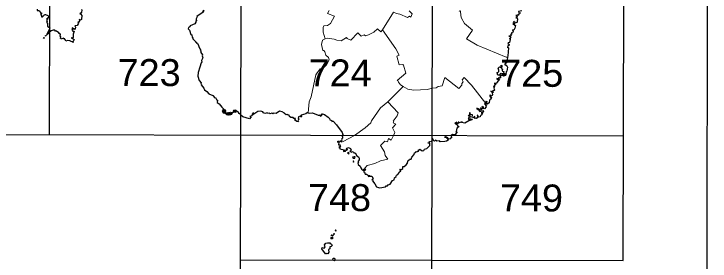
# Model space of a CAD drawing. Extents: x 483855 to 488461, y 4388206 to 4391419.
# Drawn here: x 487957 to 488461, y 4390095 to 4390274 of the extents above; entities that cross this region are included whole.
import ezdxf
from ezdxf.enums import TextEntityAlignment as Align

# ---------------------------------------------------------------- set-up
doc = ezdxf.new("R2010")
doc.units = 0
doc.header["$LTSCALE"] = 4
doc.header["$PDMODE"] = 32
doc.header["$PDSIZE"] = 2
doc.linetypes.add('DOTTED', pattern=[1.5, 0.3, -1.2])
for name, color, linetype, lineweight in [('1', 7, 'Continuous', 13), ('2', 7, 'DOTTED', 13), ('3', 7, 'Continuous', 25)]:
    doc.layers.add(name, color=color, linetype=linetype, lineweight=lineweight)

msp = doc.modelspace()

# ---------------------------------------------------------------- linework, layer by layer
at = {"layer": '1', "lineweight": 25}
for p, q in [((487982.46, 4390186.29), (487983.15, 4390547.6)), ((488120.68, 4390005.39), (488121.71, 4390547.34)), ((488259.24, 4390005.13), (488260.27, 4390547.08)), ((488397.97, 4390095.17), (488398.83, 4390546.81)), ((487843.9, 4390186.56), (488398.14, 4390185.5)), ((488120.85, 4390095.7), (488397.97, 4390095.17))]:
    msp.add_line(p, q, dxfattribs=at)
msp.add_lwpolyline([(483860.86, 4391419.44), (488460.85, 4391410.69), (488454.76, 4388205.69), (483854.77, 4388214.44)], close=True, dxfattribs=at)
at = {"layer": '3', "lineweight": 13}
msp.add_line((488238.58, 4390221.21), (488227.38, 4390210.16), dxfattribs=at)
at = {"layer": '3'}
for points in [[(487973.52, 4390277.25), (487973.36, 4390276.19), (487974.61, 4390276.26), (487975.37, 4390275.8), (487975.64, 4390274.84), (487976.5, 4390274.46), (487976.69, 4390273.83), (487975.88, 4390273.77), (487976.33, 4390273.63), (487976, 4390272.99), (487976.48, 4390272.85), (487976.5, 4390271.77), (487977.2, 4390271.6), (487978.56, 4390272.83)], [(488005.48, 4390277.01), (488005.76, 4390276.78), (488005.64, 4390274.75), (488004.45, 4390273.84), (488005.27, 4390273.88), (488005.24, 4390273.2), (488005.68, 4390272.99), (488005.44, 4390269.65), (488004.93, 4390269.15), (488003.86, 4390269.82), (488004.14, 4390268.43), (488003.66, 4390267.67), (488003.48, 4390267.97), (488002.96, 4390267.83), (488003.07, 4390267.53)], [(488093.48, 4390276.48), (488094.07, 4390276.17), (488093.76, 4390275.62), (488093.09, 4390275.98), (488093.76, 4390275.51), (488093.65, 4390275.07), (488089.15, 4390272), (488089.34, 4390271.55), (488088.6, 4390270.25), (488088.67, 4390269.33), (488089.01, 4390269.11), (488088.26, 4390268.59), (488088.48, 4390267.7), (488087.54, 4390266.67)], [(488324.41, 4390276.08), (488322.09, 4390275.52), (488322.38, 4390274.67), (488323.48, 4390274.52), (488322.87, 4390274.04), (488322.24, 4390274.33), (488322.04, 4390273.85), (488322.43, 4390273.11), (488322.14, 4390272.77), (488321.19, 4390272.97), (488321.41, 4390272.55), (488320.07, 4390272.67), (488321.28, 4390271.99), (488320.58, 4390271.13)], [(487978.56, 4390272.83), (487978.78, 4390273.28), (487979.5, 4390273.28), (487981.19, 4390272.74), (487981.62, 4390272.24), (487981.36, 4390270.86), (487981.03, 4390270.9), (487981.38, 4390270.78), (487980.98, 4390270.65), (487981.3, 4390270.49), (487981, 4390270.52), (487981.19, 4390270.07), (487980.77, 4390269.88), (487980.71, 4390270.76), (487980.45, 4390269), (487980.76, 4390268.59), (487980.28, 4390267.86), (487980.82, 4390266.8), (487980.88, 4390264.83), (487982.01, 4390264.27)], [(488320.58, 4390271.13), (488320.2, 4390270.99), (488321.13, 4390270.87), (488321.33, 4390269.84), (488320.76, 4390267.37), (488319.1, 4390267.75), (488318.59, 4390268.42), (488318.73, 4390267.4), (488318.01, 4390267.08), (488319.05, 4390267.08), (488319.68, 4390266.57), (488318.08, 4390266.27), (488318.71, 4390266.34), (488319.16, 4390265.56), (488319.97, 4390265.49), (488319.33, 4390263.52)], [(488003.07, 4390267.53), (488003.35, 4390267.41), (488003.21, 4390266.63), (488002.31, 4390265.37), (488000.81, 4390265.27), (488001.32, 4390264.14), (488000.99, 4390262.69), (488000.57, 4390262.44), (488000.56, 4390263.07), (487999.29, 4390263.17), (487999.79, 4390263.24), (487998.85, 4390263.72), (487999.15, 4390263.02), (487998.63, 4390262.96), (487999.15, 4390262.31), (487998.83, 4390261.62), (487999.46, 4390261.4)], [(488087.54, 4390266.67), (488084.38, 4390265.05), (488084.07, 4390264.42), (488083.07, 4390263.91), (488082.74, 4390263), (488083.67, 4390261.9), (488084.75, 4390258.95), (488085.39, 4390258.57), (488085.79, 4390256.72), (488086.1, 4390256.62)], [(487982, 4390261.72), (487980.2, 4390258.58), (487981.98, 4390259.98)], [(487989.09, 4390260.07), (487987.42, 4390261.37), (487986.63, 4390261.33), (487986.31, 4390261.93), (487985.02, 4390262.13), (487983.63, 4390261.45), (487981.98, 4390259.98)], [(487982.01, 4390264.27), (487982.61, 4390264.17), (487982.2, 4390264.05), (487982.73, 4390263.76), (487982, 4390261.72)], [(487997.27, 4390254.21), (487995.45, 4390254.46), (487994.12, 4390254.05), (487993.68, 4390255.15), (487993.16, 4390255.35), (487993.46, 4390255.62), (487992.94, 4390255.66), (487992.54, 4390256.22), (487990.8, 4390255.55), (487990.69, 4390255.98), (487990.26, 4390255.88), (487990.61, 4390257.26), (487990.21, 4390257.87), (487990.43, 4390258.87), (487989.8, 4390259.69), (487989.11, 4390259.71), (487989.09, 4390260.07)], [(487999.46, 4390261.4), (488000.16, 4390261.26), (487999.44, 4390259.04), (487999.53, 4390256.99), (487999.08, 4390256.24), (487998.16, 4390256.37), (488000.3, 4390255.3), (487999.6, 4390253.84), (487999.82, 4390253.55), (487999.22, 4390253), (487999.24, 4390253.9), (487998, 4390253.58), (487998.09, 4390253.84), (487997.66, 4390253.68), (487997.27, 4390254.21)], [(488319.33, 4390263.52), (488318.75, 4390262.1), (488317.79, 4390262.26), (488318.15, 4390261.02), (488317.63, 4390260.03), (488316.95, 4390259.99), (488317.08, 4390258.93), (488316.29, 4390258.84), (488316.7, 4390257.86), (488315.17, 4390257.66), (488316.27, 4390257.15), (488316.44, 4390256.65), (488315.53, 4390255.84), (488316.05, 4390255.9), (488316.1, 4390255.35), (488315.58, 4390253.07), (488315.05, 4390252.78)], [(488086.1, 4390256.62), (488086.19, 4390255.76), (488088.33, 4390253.54), (488088.19, 4390253.28), (488088.78, 4390253.42), (488088.93, 4390252.67), (488089.83, 4390252.02), (488090.98, 4390248.89)], [(488315.05, 4390252.78), (488314.68, 4390252.87), (488314.28, 4390252.17), (488315.27, 4390251.53), (488315.17, 4390250.72), (488314.4, 4390250.56), (488314, 4390249.77), (488314.23, 4390249.33), (488314.67, 4390249.69), (488314.73, 4390249.3), (488314.44, 4390243.32), (488314.12, 4390242.51)], [(488090.98, 4390248.89), (488091.84, 4390248.26), (488091.43, 4390247.46), (488091.97, 4390246.84), (488092.01, 4390245.82), (488093.19, 4390244.24), (488092.84, 4390243.53), (488093.44, 4390241.91), (488092.54, 4390240.14), (488092.79, 4390239.17), (488092.17, 4390238.46), (488091.15, 4390235.31), (488090.09, 4390231.34)], [(488314.12, 4390242.51), (488313.69, 4390238.54), (488312.29, 4390237.33), (488312.23, 4390236.85), (488312.87, 4390236.55), (488313.21, 4390236.83), (488313.14, 4390236.37), (488313.67, 4390236.13), (488314.1, 4390235.22), (488313.64, 4390232.27), (488313.11, 4390231.89), (488313.3, 4390231.48)], [(488306.69, 4390230.91), (488306.74, 4390231.36), (488307.89, 4390231.85), (488307.8, 4390232.92), (488308.18, 4390233.01), (488307.83, 4390233.11), (488307.4, 4390234.42), (488308.3, 4390235.47), (488309.26, 4390234.94), (488309.59, 4390235.37), (488309.58, 4390236.63), (488309.97, 4390236.45), (488309.87, 4390234.35), (488310.47, 4390233.8), (488310.28, 4390232.68), (488310.45, 4390232.22), (488311.36, 4390232.08), (488311.33, 4390230.91)], [(488090.09, 4390231.34), (488089.71, 4390228.8), (488090.77, 4390225.45), (488092.15, 4390223.97), (488091.92, 4390223.4), (488092.49, 4390222.78), (488092.33, 4390222.44), (488094.22, 4390220.1), (488094.73, 4390218.81), (488096.41, 4390217.62)], [(488306.69, 4390230.91), (488306.67, 4390230.03), (488307.43, 4390229.72), (488308.46, 4390229.7), (488309.47, 4390230.75), (488310.2, 4390230.6), (488310.45, 4390230.16), (488309.5, 4390228.88), (488308.8, 4390228.92), (488308.98, 4390227.58), (488308.33, 4390227.31), (488307.76, 4390227.9), (488307.78, 4390227.16), (488307.4, 4390226.8), (488306.45, 4390226.88), (488306.42, 4390226.51), (488307.15, 4390226.16), (488308.41, 4390226.42), (488306.42, 4390224)], [(488311.33, 4390230.91), (488311.22, 4390229.2), (488311.55, 4390228.92), (488312.79, 4390229.42), (488313.2, 4390230.14), (488313.08, 4390230.92)], [(488313.3, 4390231.48), (488313, 4390231.39), (488313.08, 4390230.92)], [(488306.42, 4390224), (488306.1, 4390223.36), (488304.56, 4390223.42), (488305.55, 4390223.07), (488303.87, 4390221.13), (488304.66, 4390221.51), (488304.24, 4390220), (488304.78, 4390218.66), (488304.42, 4390218.23), (488303.34, 4390218.03), (488303.4, 4390217.62), (488302.9, 4390217.42), (488302.15, 4390217.76), (488302.92, 4390216.9), (488303.84, 4390217.45), (488303.98, 4390217.18), (488303.05, 4390216.48), (488303.31, 4390215.3), (488303.06, 4390214.59), (488301.95, 4390214.1), (488301.89, 4390214.36)], [(488096.41, 4390217.62), (488097.85, 4390215.88), (488100.68, 4390214.7), (488102.11, 4390213.02), (488102.68, 4390213.12), (488103.25, 4390211.78), (488103.96, 4390211.28), (488103.81, 4390209.6), (488105.31, 4390208.61), (488107.2, 4390206.31)], [(488301.89, 4390214.36), (488301.58, 4390215.2), (488301.58, 4390214.35), (488301.18, 4390214.18), (488301.64, 4390214.03), (488301.88, 4390213.29), (488302.19, 4390213.65), (488302.41, 4390213.34), (488301.92, 4390212), (488301.2, 4390211.34), (488300.74, 4390209.46), (488299.64, 4390208.39), (488299.23, 4390208.9), (488299.44, 4390210.33), (488299.05, 4390209.75), (488298.64, 4390210.52), (488298.36, 4390210.4), (488298.71, 4390209.39), (488298.47, 4390208.98)], [(488107.2, 4390206.31), (488108.85, 4390204.6), (488109.08, 4390202.82), (488110.14, 4390201.46), (488114.33, 4390201.95), (488117.22, 4390203.94), (488118.88, 4390203.15), (488119.39, 4390201.95), (488120.05, 4390201.77), (488120.7, 4390200.72)], [(488293.53, 4390204.81), (488291.88, 4390205.51), (488291.89, 4390204.74), (488292.16, 4390205.07), (488292.05, 4390204.59), (488292.52, 4390204.98), (488292.34, 4390204.64), (488292.66, 4390204.91), (488292.66, 4390204.5), (488292.87, 4390204.81), (488292.7, 4390204.49), (488293.39, 4390204.5), (488293.21, 4390204.22), (488294.08, 4390203.15), (488296.37, 4390203.91), (488296.64, 4390203.12), (488296.45, 4390202.58), (488295.12, 4390202.06), (488296.16, 4390201.93), (488295.51, 4390201.38), (488295.43, 4390200.58), (488294.58, 4390200.24), (488294.31, 4390199.27), (488293.23, 4390198.87), (488292.7, 4390199.42)], [(488298.47, 4390208.98), (488298.69, 4390208.05), (488297.52, 4390208.55), (488298.9, 4390207.01), (488298.45, 4390206.9), (488298.63, 4390206.36), (488297.54, 4390204.96), (488296.89, 4390205.29), (488296.62, 4390206.43), (488296.23, 4390206.21), (488295.64, 4390206.87), (488296.3, 4390205.5), (488296.06, 4390204.72), (488294.55, 4390205.83), (488295.15, 4390204.38), (488294.22, 4390204.11), (488293.53, 4390204.81)], [(488133.32, 4390203.04), (488129.72, 4390200.58), (488129.48, 4390201.3), (488130.13, 4390202.18), (488129.56, 4390201.95), (488128.83, 4390199.88), (488127.46, 4390199.45), (488128.35, 4390199.12), (488127.28, 4390197.86), (488122.34, 4390199.27), (488120.7, 4390200.72)], [(488152.6, 4390201.55), (488152.49, 4390201.97), (488150.91, 4390202.95), (488149.06, 4390203.32), (488146.62, 4390201.52), (488144.7, 4390201.9), (488144.23, 4390201.49), (488143.43, 4390201.83), (488142.29, 4390201.49), (488141.61, 4390201.87), (488140.18, 4390201.55), (488139.95, 4390202.14), (488138.4, 4390201.68), (488137.29, 4390202.06), (488136.92, 4390202.75), (488136.09, 4390203.13), (488134.92, 4390203.33), (488133.32, 4390203.04)], [(488161.42, 4390195.8), (488161.35, 4390196.16), (488160.14, 4390196.7), (488160.47, 4390198.03), (488159.38, 4390197.99), (488158.91, 4390198.7), (488157.27, 4390198.63), (488156.25, 4390199.36), (488155.95, 4390200.44), (488155.32, 4390200.31), (488154.67, 4390200.93), (488153.79, 4390200.56), (488152.6, 4390201.55)], [(488169.64, 4390202.1), (488168.91, 4390202.14), (488167.98, 4390201.34), (488164.73, 4390200.51), (488164.92, 4390199.98), (488164.41, 4390200.11), (488164.75, 4390199.8), (488164.37, 4390199.95), (488164.61, 4390199.65), (488164.16, 4390199.59), (488164.52, 4390199.34), (488165.15, 4390199.81), (488164.54, 4390199.19), (488163.92, 4390199.6), (488162.83, 4390199.13), (488162.5, 4390198.13), (488162.99, 4390197.81), (488162.46, 4390196.66), (488162.76, 4390196.11), (488162.32, 4390195.59), (488162.16, 4390195.93), (488161.42, 4390195.8)], [(488169.64, 4390202.1), (488170.78, 4390201.77), (488172.86, 4390202.14), (488177, 4390200.44), (488177.97, 4390200.38), (488178.64, 4390199.68), (488179.07, 4390199.88), (488178.19, 4390200.46), (488178.67, 4390200.21), (488178.5, 4390200.5), (488178.81, 4390200.32), (488178.64, 4390200.61), (488179.08, 4390200.55), (488179.63, 4390201.4), (488179.83, 4390201.09)], [(488179.83, 4390201.09), (488178.97, 4390200.02), (488180.04, 4390201.48), (488181.59, 4390200.84), (488184.16, 4390199.09), (488185.23, 4390197.99), (488185.44, 4390197.03), (488186.82, 4390196.51), (488186.82, 4390195.85), (488187.81, 4390195.99), (488190.27, 4390193.36)], [(488285.84, 4390199.95), (488286.68, 4390200.04), (488287.12, 4390199.66), (488286.56, 4390198.27), (488285.71, 4390198.57), (488286.16, 4390197.8), (488285.94, 4390197.31), (488287.44, 4390197.87), (488288.53, 4390197.43), (488288.38, 4390196.96), (488286.16, 4390196.41), (488283.16, 4390194.66), (488280.78, 4390195), (488281.2, 4390195.65), (488279.22, 4390194.95), (488278.9, 4390194.95), (488279.05, 4390195.61), (488278.86, 4390195.39)], [(488292.7, 4390199.42), (488292.77, 4390199.86), (488292.16, 4390200.34), (488292.56, 4390198.74), (488291.76, 4390198.03), (488291.24, 4390198.42), (488290.59, 4390198.07), (488290.16, 4390198.36), (488290.56, 4390199.35), (488288.73, 4390198.51), (488288.43, 4390198.97), (488288.77, 4390200.61), (488287.31, 4390200.92), (488287.02, 4390202.01), (488286.63, 4390202.21), (488286.57, 4390200.61), (488287.05, 4390200.65), (488286.14, 4390199.96), (488285.56, 4390200.32), (488285.84, 4390199.95)], [(488278.86, 4390195.39), (488278.45, 4390195.31), (488278.39, 4390194.37), (488277.4, 4390194.39), (488277.35, 4390195.34), (488275.98, 4390194.56), (488277.91, 4390193.43), (488277.54, 4390192.96), (488277.99, 4390193.03), (488278.84, 4390192.3), (488278.62, 4390191.63), (488277.53, 4390190.96), (488277.04, 4390188.5), (488276.66, 4390188.23), (488277.56, 4390188.24), (488277.04, 4390187.48)], [(488190.27, 4390193.36), (488194.33, 4390187.91), (488194.79, 4390186.54), (488194.51, 4390185.8)], [(488193.57, 4390181.16), (488194.4, 4390182.52), (488194.04, 4390183.22), (488194.79, 4390184), (488194.9, 4390184.95), (488194.35, 4390185.32), (488194.51, 4390185.8)], [(488273.29, 4390185.72), (488273.67, 4390184.12), (488272.9, 4390183.79), (488272.49, 4390183.02), (488271.36, 4390183.26), (488270.67, 4390184.13), (488270.17, 4390184.05), (488269.22, 4390185.25), (488269.55, 4390184.5), (488268.47, 4390184.46), (488269.61, 4390184.39), (488270.06, 4390183.72), (488270.63, 4390183.61), (488271.12, 4390182.36), (488269.88, 4390181.56), (488268.77, 4390181.42)], [(488277.04, 4390187.48), (488276.31, 4390186.16), (488274.27, 4390186.35), (488273.29, 4390185.72)], [(488193.57, 4390181.16), (488192.74, 4390181.78), (488192.89, 4390181.24), (488191.95, 4390180.88), (488191.74, 4390178.97), (488193, 4390178.94), (488192.67, 4390178.38), (488193.04, 4390178.11), (488192.78, 4390177.53), (488191.9, 4390177.1), (488192.63, 4390176.9), (488192.64, 4390175.96), (488195.84, 4390175.37), (488195.78, 4390174.67), (488195.04, 4390174.32), (488195.6, 4390174.13)], [(488247.42, 4390173.28), (488247.89, 4390174.31), (488248.26, 4390173.78), (488249.75, 4390174.41), (488249.78, 4390174.76), (488249.16, 4390174.8), (488250.52, 4390175.85), (488252.36, 4390174.62), (488253.61, 4390174.91), (488254.04, 4390175.88), (488255.79, 4390176.35), (488257.96, 4390178.38), (488257.85, 4390180.11)], [(488257.85, 4390180.11), (488256.73, 4390180.16), (488256.65, 4390180.48), (488257.45, 4390180.62), (488257.5, 4390181.04), (488257.12, 4390181.19), (488259.39, 4390181.56), (488259.86, 4390183.62)], [(488268.77, 4390181.42), (488265.46, 4390181.19), (488264.76, 4390181.76), (488262.98, 4390181.57), (488261.89, 4390182.25), (488261.28, 4390181.7), (488260.69, 4390181.82), (488259.86, 4390183.62)], [(488195.6, 4390174.13), (488196.68, 4390174.3), (488197.24, 4390175.28), (488197.74, 4390175.18), (488198.24, 4390175.75), (488197.83, 4390175.65), (488197.87, 4390176.06), (488197.25, 4390175.63), (488197.82, 4390176.61), (488199, 4390176.94), (488200.28, 4390176.3), (488200.76, 4390175.05), (488200.28, 4390174.5), (488200.56, 4390173.95), (488201.01, 4390173.66), (488202.25, 4390174.02), (488202.81, 4390173.16), (488203.79, 4390173.17)], [(488203.79, 4390173.17), (488204.93, 4390171.02), (488206.17, 4390170.22), (488206.77, 4390169.34), (488206.79, 4390168.02), (488205.67, 4390166.65), (488206.18, 4390166.31), (488205.74, 4390165.55), (488205.94, 4390164.62), (488207.44, 4390163.45), (488207.83, 4390162.16), (488208.46, 4390161.64), (488208.29, 4390161.21), (488209.13, 4390160.67), (488210.75, 4390161.72)], [(488240.74, 4390164.4), (488241.72, 4390165.62), (488241.57, 4390166.14), (488242.18, 4390167.63), (488242.97, 4390167.77), (488243.09, 4390168.56), (488244.41, 4390168.44), (488244.87, 4390170), (488246.63, 4390171.99), (488246.81, 4390173.03), (488247.42, 4390173.28)], [(488233.36, 4390156.05), (488233.81, 4390156.94), (488234.76, 4390157.36), (488235.38, 4390158.44), (488235.1, 4390158.56), (488235.69, 4390158.78), (488235.84, 4390159.39), (488236.76, 4390160.17), (488236.18, 4390161.3), (488237.4, 4390161.01), (488238.36, 4390161.91), (488238.28, 4390163.21), (488239.24, 4390163.27), (488240.74, 4390164.4)], [(488210.75, 4390161.72), (488211.28, 4390160.9), (488209.91, 4390159.54), (488210.62, 4390159.25), (488210.98, 4390157.8), (488211.96, 4390157.66), (488212.73, 4390156.98), (488213.3, 4390157.22), (488213.41, 4390156.78), (488214.08, 4390156.78), (488214.34, 4390156.54), (488213.92, 4390156.14), (488215.86, 4390156.33), (488216.73, 4390154.62), (488216.53, 4390153.97), (488215.77, 4390153.55), (488216.46, 4390153.59), (488216.34, 4390152.9), (488218.14, 4390150.61)], [(488218.14, 4390150.61), (488219.29, 4390148.52), (488220.66, 4390148.08), (488221.72, 4390147.89), (488225.71, 4390148.62), (488226.18, 4390149.18), (488227.09, 4390149.17), (488227.66, 4390149.86), (488229.25, 4390150.54), (488230.88, 4390153.08), (488231.96, 4390153.63), (488232.19, 4390154.96), (488233.36, 4390156.05)], [(488184.04, 4390100.06), (488183.11, 4390100.31), (488182.92, 4390099.94), (488182.17, 4390099.91), (488179.66, 4390103.58), (488179.9, 4390104.54), (488181.3, 4390104.19), (488182.05, 4390104.86), (488181.48, 4390105.42), (488181.84, 4390105.65), (488181.65, 4390106.54), (488182.61, 4390107.61)], [(488182.61, 4390107.61), (488183.78, 4390108), (488185.69, 4390107.85), (488185.94, 4390107.34), (488185.32, 4390107.35), (488186.56, 4390106.94), (488187.11, 4390105.96), (488186.5, 4390105.35), (488185.4, 4390105.06), (488185.7, 4390104.88), (488185.22, 4390104.53), (488185.57, 4390103.79), (488184.56, 4390102.75), (488184.69, 4390101.27), (488184.04, 4390100.06)], [(488187.59, 4390095.48), (488187.75, 4390096.73), (488188.47, 4390096.83), (488189.08, 4390096.6), (488188.88, 4390096.19), (488189.35, 4390095.49)], [(488189.35, 4390095.49), (488188.84, 4390094.91), (488187.59, 4390095.48)]]:
    msp.add_lwpolyline(points, dxfattribs=at)
at = {"layer": '3', "lineweight": 13}
for points in [[(488182.06, 4390255.76), (488180.7, 4390260.67), (488180.65, 4390263.85), (488181.13, 4390265.13), (488183.84, 4390265.36), (488185.93, 4390266.77), (488188.82, 4390272.26), (488183.67, 4390274.07), (488185.02, 4390276.15)], [(488223.49, 4390262.26), (488231.51, 4390274.97), (488233.72, 4390274.09), (488236.1, 4390273.7), (488241.61, 4390271.1), (488243.07, 4390272.24), (488244.07, 4390271.53), (488245.11, 4390273.86), (488242.92, 4390276.07)], [(488279.15, 4390276.06), (488279.47, 4390275.76), (488280.01, 4390275.93), (488280.25, 4390272.48), (488280.82, 4390270.68), (488282.93, 4390266.87), (488288.86, 4390262.03), (488284.34, 4390255.64), (488292.14, 4390251.04), (488313.16, 4390242.51), (488314.12, 4390242.51)], [(488190.4, 4390254.79), (488193.62, 4390254.18), (488197.44, 4390256.76), (488197.95, 4390255.89), (488200.75, 4390254.72), (488205.75, 4390260.01), (488208.04, 4390257.72), (488210.31, 4390258.56), (488211.26, 4390257.8), (488213.5, 4390258.56), (488217.37, 4390260.6), (488219.88, 4390262.88), (488222.33, 4390260.72), (488223.49, 4390262.26)], [(488223.49, 4390262.26), (488233.19, 4390248.55), (488235.57, 4390243.81), (488233.9, 4390243.11), (488235.57, 4390236.9), (488238.35, 4390237.07), (488238.79, 4390236.57), (488240.59, 4390230.9)], [(488182.06, 4390255.76), (488180.21, 4390254.77), (488179.48, 4390251.53), (488180.39, 4390247.38), (488180.98, 4390247.28), (488181.84, 4390246.34), (488182.55, 4390243.94), (488184.58, 4390242.27), (488185.03, 4390240.59), (488182.93, 4390236.78), (488180.82, 4390234.73), (488178.52, 4390233.92), (488176.37, 4390231.02)], [(488182.06, 4390255.76), (488183.64, 4390256.22), (488188.66, 4390255.47), (488190.4, 4390254.79)], [(488169.64, 4390202.1), (488170.54, 4390210.13), (488171.91, 4390213.62), (488175.35, 4390229.54), (488176.37, 4390231.02)], [(488238.58, 4390221.21), (488236.66, 4390222.43), (488235.08, 4390224.43), (488234.76, 4390225.53), (488234.15, 4390225.66), (488240.59, 4390230.9)], [(488259.88, 4390219.98), (488262.52, 4390220.27), (488263.97, 4390221.12), (488266.74, 4390221.63), (488268.65, 4390227.67), (488278.8, 4390219.86), (488280.92, 4390222.14), (488280.95, 4390223.43), (488281.97, 4390224.53), (488281.26, 4390226.14), (488282.72, 4390227.71), (488288.08, 4390222.18), (488298.47, 4390208.98)], [(488238.58, 4390221.21), (488241.9, 4390219.28), (488246.35, 4390218.48), (488255.95, 4390218.96), (488259.88, 4390219.98)], [(488227.38, 4390210.16), (488222.14, 4390205.8), (488215.71, 4390196.3), (488215.06, 4390194.79), (488211.04, 4390191.3), (488203.41, 4390185.78)], [(488227.38, 4390210.16), (488234.84, 4390202.16), (488234.24, 4390200.01), (488231.26, 4390196.09), (488231.67, 4390195.83), (488231.42, 4390194.89), (488233.14, 4390193.82), (488230.92, 4390191.34), (488232.51, 4390187.94), (488231.51, 4390185.75)], [(488203.41, 4390185.78), (488195.19, 4390181.43), (488193.68, 4390180.89), (488193.57, 4390181.16)], [(488231.51, 4390185.75), (488229.82, 4390182.24), (488227.97, 4390183.46), (488227.09, 4390181.18), (488225.16, 4390181.55), (488222.12, 4390178.48), (488225.08, 4390173.97), (488225.47, 4390171.31), (488227.42, 4390168.59), (488222.23, 4390167.39), (488218.12, 4390165.49), (488212.43, 4390163.86), (488210.68, 4390162.1), (488210.75, 4390161.72)]]:
    msp.add_lwpolyline(points, dxfattribs=at)
at = {"layer": '3'}
for points in [[(487978.45, 4390256.58), (487978.48, 4390256.22), (487978.01, 4390256.01)], [(487979.55, 4390258.25), (487979.88, 4390258.18), (487979.59, 4390257.6)], [(488191.68, 4390181.63), (488190.77, 4390181.07), (488191.59, 4390181.23)], [(488199.93, 4390174.36), (488199.89, 4390174.11), (488200.21, 4390174.38)], [(488198.82, 4390173.4), (488198.29, 4390172.87), (488199.08, 4390172.43), (488199.43, 4390172.86)], [(488203.09, 4390170.36), (488201.92, 4390169.97), (488202.32, 4390169.17), (488203.5, 4390169.21), (488203.69, 4390170.18)], [(488202.33, 4390167.22), (488202.56, 4390166.28), (488202.76, 4390166.8), (488202.59, 4390167.4)], [(488213.4, 4390156.18), (488213.41, 4390155.8), (488213.75, 4390156.17)], [(488186.85, 4390113.63), (488187.98, 4390113.53), (488187.39, 4390112.85), (488186.32, 4390113.33)], [(488188.43, 4390114.58), (488188.83, 4390114.43), (488188.32, 4390113.99)], [(488189.5, 4390117.29), (488189.24, 4390116.77), (488189.79, 4390116.48), (488189.95, 4390116.8)], [(488187.37, 4390112.06), (488187.39, 4390110.79), (488186.2, 4390110.91), (488186.59, 4390111.45), (488186.26, 4390111.9)]]:
    msp.add_lwpolyline(points, close=True, dxfattribs=at)
for p in [(488311.14, 4390229.79), (488108.8, 4390203.5), (488116.57, 4390203.41), (488108.97, 4390202.73), (488111.61, 4390201.32), (488112.42, 4390201.48), (488113.44, 4390201.62)]:
    msp.add_point(p, dxfattribs=at)

# ---------------------------------------------------------------- texts
at = {"layer": '2', "width": 1.05}
for s, p in [('723', (488054.51, 4390221.54)), ('724', (488192.87, 4390221.29)), ('725', (488331.63, 4390221.01)), ('748', (488192.44, 4390130.97)), ('749', (488331.46, 4390130.71))]:
    msp.add_text(s, height=19.5, rotation=359.891, dxfattribs=at).set_placement(p, align=Align.CENTER)

doc.saveas('drawing.dxf')
